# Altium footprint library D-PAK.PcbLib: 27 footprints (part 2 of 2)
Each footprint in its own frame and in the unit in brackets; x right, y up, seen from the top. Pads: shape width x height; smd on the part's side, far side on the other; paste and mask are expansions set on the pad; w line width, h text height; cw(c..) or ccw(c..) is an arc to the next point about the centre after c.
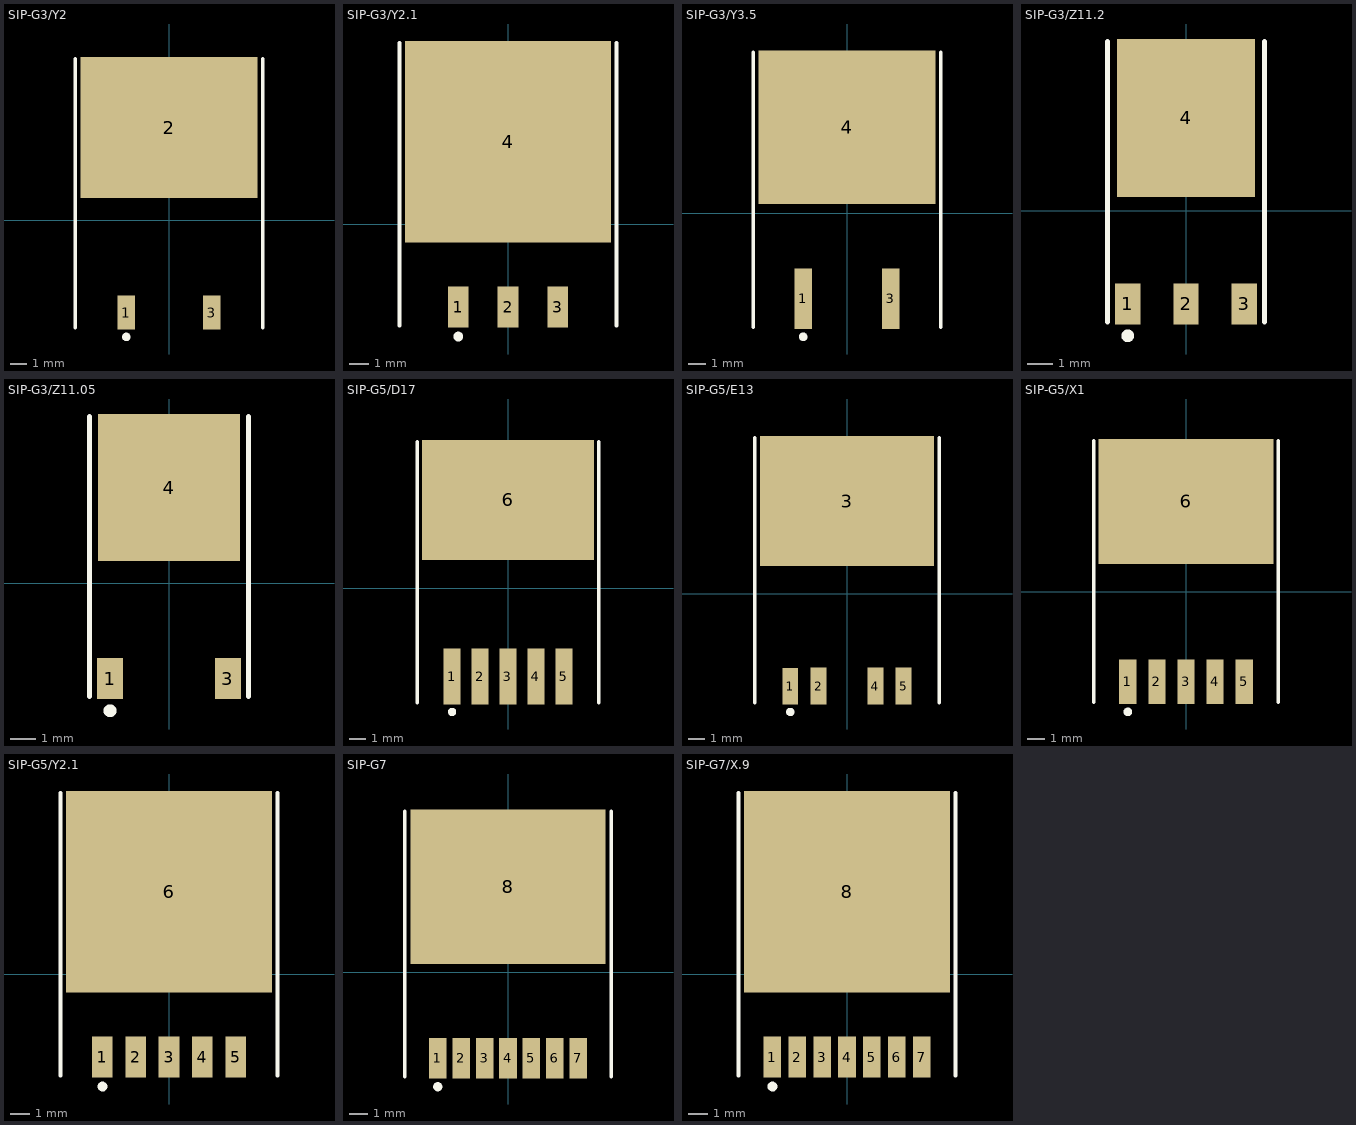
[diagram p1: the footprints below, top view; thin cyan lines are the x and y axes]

## SIP-G3/Y2 [mm]
pads (3):
  rect 1.05x2 smd: 1(-2.54,-5.5) 3(2.54,-5.5)
  rect 10.55x8.4 smd: 2(0,5.5)
Top Overlay:
  circle w0.25: c-2.54,-6.95 r0.125
  lines w0.2: -5.575,-6.4 -5.575,9.6 ; 5.575,-6.4 5.575,9.6

## SIP-G3/Y2.1 [mm]
pads (4):
  rect 1.05x2.1 smd: 1(-2.54,-4.225) 2(0,-4.225) 3(2.54,-4.225)
  rect 10.5x10.3 smd: 4(0,4.225)
Top Overlay:
  circle w0.25: c-2.54,-5.725 r0.125
  lines w0.2: -5.55,-5.175 -5.55,9.275 ; 5.55,-5.175 5.55,9.275

## SIP-G3/Y3.5 [mm]
pads (3):
  rect 1x3.5 smd: 1(-2.54,-4.975) 3(2.54,-4.975)
  rect 10.25x8.9 smd: 4(0,4.975)
Top Overlay:
  circle w0.25: c-2.54,-7.175 r0.125
  lines w0.2: -5.425,-6.625 -5.425,9.325 ; 5.425,-6.625 5.425,9.325

## SIP-G3/Z11.2 [mm]
pads (4):
  rect 1x1.6 smd: 1(-2.285,-3.65) 2(0,-3.65) 3(2.285,-3.65)
  rect 5.4x6.2 smd: 4(0,3.65)
Top Overlay:
  circle w0.25: c-2.285,-4.9 r0.125
  lines w0.2: -3.085,-4.35 -3.085,6.65 ; 3.085,-4.35 3.085,6.65

## SIP-G3/Z11.05 [mm]
pads (3):
  rect 1x1.6 smd: 1(-2.285,-3.7) 3(2.285,-3.7)
  rect 5.5x5.7 smd: 4(0,3.7)
Top Overlay:
  circle w0.25: c-2.285,-4.95 r0.125
  lines w0.2: -3.085,-4.4 -3.085,6.45 ; 3.085,-4.4 3.085,6.45

## SIP-G5/D17 [mm]
pads (6):
  rect 1.05x3.4 smd: 1(-3.4,-5.375) 2(-1.7,-5.375) 3(0,-5.375) 4(1.7,-5.375) 5(3.4,-5.375)
  rect 10.45x7.3 smd: 6(0,5.375)
Top Overlay:
  circle w0.25: c-3.4,-7.525 r0.125
  lines w0.2: -5.525,-6.975 -5.525,8.925 ; 5.525,-6.975 5.525,8.925

## SIP-G5/E13 [mm]
pads (5):
  rect 0.95x2.2 smd: 1(-3.4,-5.55) 2(-1.7,-5.55) 4(1.7,-5.55) 5(3.4,-5.55)
  rect 10.45x7.8 smd: 3(0,5.55)
Top Overlay:
  circle w0.25: c-3.4,-7.1 r0.125
  lines w0.2: -5.525,-6.55 -5.525,9.35 ; 5.525,-6.55 5.525,9.35

## SIP-G5/X1 [mm]
pads (6):
  rect 1x2.6 smd: 1(-3.4,-5.275) 2(-1.7,-5.275) 3(0,-5.275) 4(1.7,-5.275) 5(3.4,-5.275)
  rect 10.2x7.3 smd: 6(0,5.275)
Top Overlay:
  circle w0.25: c-3.4,-7.025 r0.125
  lines w0.2: -5.4,-6.475 -5.4,8.825 ; 5.4,-6.475 5.4,8.825

## SIP-G5/Y2.1 [mm]
pads (6):
  rect 1.05x2.1 smd: 1(-3.4,-4.225) 2(-1.7,-4.225) 3(0,-4.225) 4(1.7,-4.225) 5(3.4,-4.225)
  rect 10.5x10.3 smd: 6(0,4.225)
Top Overlay:
  circle w0.25: c-3.4,-5.725 r0.125
  lines w0.2: -5.55,-5.175 -5.55,9.275 ; 5.55,-5.175 5.55,9.275

## SIP-G7 [mm]
pads (8):
  rect 0.95x2.2 smd: 1(-3.81,-4.65) 2(-2.54,-4.65) 3(-1.27,-4.65) 4(0,-4.65) 5(1.27,-4.65) 6(2.54,-4.65) 7(3.81,-4.65)
  rect 10.6x8.4 smd: 8(0,4.65)
Top Overlay:
  circle w0.25: c-3.81,-6.2 r0.125
  lines w0.2: -5.6,-5.65 -5.6,8.75 ; 5.6,-5.65 5.6,8.75

## SIP-G7/X.9 [mm]
pads (8):
  rect 0.9x2.1 smd: 1(-3.81,-4.225) 2(-2.54,-4.225) 3(-1.27,-4.225) 4(0,-4.225) 5(1.27,-4.225) 6(2.54,-4.225) 7(3.81,-4.225)
  rect 10.5x10.3 smd: 8(0,4.225)
Top Overlay:
  circle w0.25: c-3.81,-5.725 r0.125
  lines w0.2: -5.55,-5.175 -5.55,9.275 ; 5.55,-5.175 5.55,9.275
